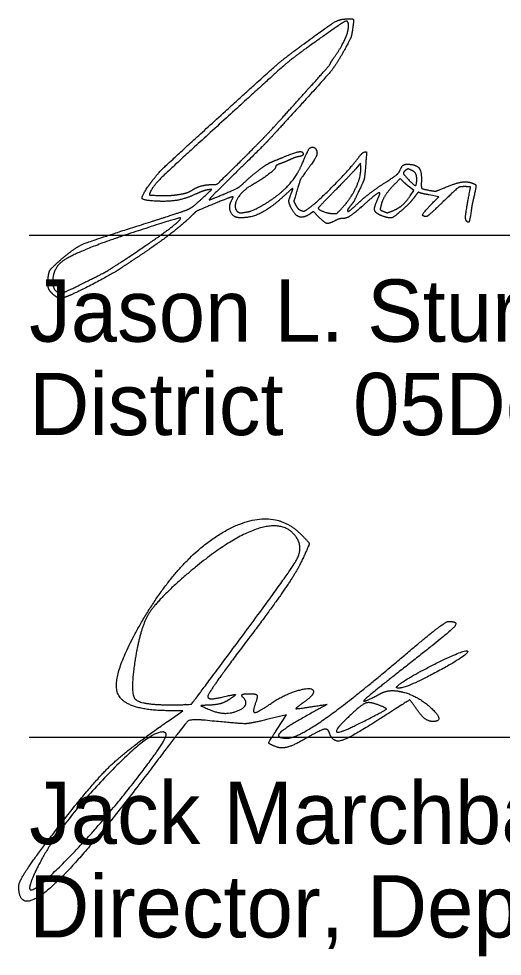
# Model space of a CAD drawing. Extents: x 0 to 34, y 0 to 22.
# Drawn here: x 24.451 to 25.538, y 5.969 to 8.077 of the extents above; entities that cross this region are included whole.
import ezdxf

# ---------------------------------------------------------------- set-up
doc = ezdxf.new("R2010")
doc.units = 0
doc.layers.add('SH_Data', color=7, linetype='Continuous')
doc.layers.add('SH_Text', color=7, linetype='Continuous')

msp = doc.modelspace()

# ---------------------------------------------------------------- linework, layer by layer
at = {"layer": 'SH_Data'}
for p, q in [((24.4745, 7.5907), (27.9745, 7.5907)), ((24.4745, 6.4613), (27.9745, 6.4613))]:
    msp.add_line(p, q, dxfattribs=at)
for points in [[(25.22, 7.7426), (25.2196, 7.7519), (25.2085, 7.7393)], [(25.3157, 7.7106), (25.3085, 7.7177), (25.2971, 7.7061)], [(25.3307, 7.6785), (25.3392, 7.6911), (25.331, 7.6973)], [(25.3854, 7.6669), (25.3951, 7.6769), (25.3736, 7.6809)], [(25.1244, 7.6324), (25.1134, 7.6435), (25.1063, 7.6385)]]:
    msp.add_lwpolyline(points, dxfattribs=at)
for points in [[(25.0877, 8.0173), (25.1488, 8.0622), (25.1709, 8.0755), (25.1857, 8.0765)], [(25.1857, 8.0765), (25.2019, 8.0777), (25.2045, 8.0734), (25.2012, 8.0517)], [(25.1922, 8.0585), (25.1929, 8.0751), (25.1758, 8.0668), (25.1061, 8.0167)], [(25.163, 7.9942), (25.176, 8.0125), (25.1917, 8.0471), (25.1922, 8.0585)], [(25.2012, 8.0517), (25.1993, 8.0387), (25.195, 8.0282), (25.1833, 8.007)], [(24.9157, 7.8692), (25.0139, 7.9585), (25.0501, 7.9897), (25.0877, 8.0173)], [(25.1061, 8.0167), (25.0653, 7.9874), (25.0384, 7.9641), (24.9177, 7.854)], [(25.1833, 8.007), (25.1652, 7.9743), (25.1413, 7.9448), (25.0659, 7.8622)], [(25.1518, 7.977), (25.1518, 7.9778), (25.1569, 7.9856), (25.163, 7.9942)], [(25.1087, 7.9266), (25.1396, 7.9609), (25.1517, 7.975), (25.1518, 7.977)], [(25.0436, 7.8544), (25.0656, 7.8788), (25.0948, 7.9113), (25.1087, 7.9266)], [(24.7424, 7.7004), (24.7597, 7.7252), (24.7933, 7.7579), (24.9157, 7.8692)], [(24.9177, 7.854), (24.7919, 7.7393), (24.7517, 7.6998), (24.7458, 7.685)], [(25.0659, 7.8622), (25.0135, 7.8048), (24.9973, 7.7881), (24.9126, 7.7048)], [(24.9503, 7.7572), (24.9797, 7.7863), (25.0217, 7.83), (25.0436, 7.8544)], [(25.0487, 7.767), (25.073, 7.777), (25.0905, 7.7792), (25.0902, 7.7722)], [(25.0881, 7.7506), (25.1005, 7.7795), (25.1062, 7.7884), (25.1119, 7.7882)], [(25.1197, 7.7824), (25.1231, 7.7752), (25.1172, 7.7615), (25.1007, 7.7386)], [(25.1119, 7.7882), (25.1147, 7.7881), (25.1182, 7.7855), (25.1197, 7.7824)], [(24.886, 7.7042), (24.8966, 7.7044), (24.8984, 7.7059), (24.9503, 7.7572)], [(25.0183, 7.7546), (25.022, 7.756), (25.0357, 7.7616), (25.0487, 7.767)], [(25.0607, 7.76), (25.054, 7.7569), (25.0441, 7.7528), (25.0385, 7.7508)], [(25.0814, 7.7671), (25.0766, 7.7663), (25.0673, 7.7631), (25.0607, 7.76)], [(25.0902, 7.7722), (25.0901, 7.7701), (25.0862, 7.7679), (25.0814, 7.7671)], [(25.1038, 7.6516), (25.1209, 7.6637), (25.196, 7.7394), (25.2108, 7.7595)], [(25.2108, 7.7595), (25.2178, 7.769), (25.2257, 7.777), (25.2284, 7.7774)], [(25.2284, 7.7774), (25.233, 7.7781), (25.2331, 7.7763), (25.2307, 7.7471)], [(24.957, 7.7078), (24.9716, 7.722), (25.0099, 7.7512), (25.0183, 7.7546)], [(25.0283, 7.7433), (25.0281, 7.7389), (24.9978, 7.7159), (24.9741, 7.7022)], [(25.0385, 7.7508), (25.033, 7.7489), (25.0284, 7.7455), (25.0283, 7.7433)], [(25.0332, 7.6804), (25.0521, 7.695), (25.0792, 7.7297), (25.0881, 7.7506)], [(25.1007, 7.7386), (25.0844, 7.7161), (25.0838, 7.715), (25.0761, 7.6889)], [(25.2085, 7.7393), (25.2025, 7.7324), (25.181, 7.7101), (25.161, 7.6898)], [(25.1769, 7.6502), (25.1968, 7.671), (25.2209, 7.7226), (25.22, 7.7426)], [(25.2307, 7.7471), (25.2286, 7.7208), (25.2269, 7.7133), (25.2202, 7.6992)], [(25.3074, 7.7345), (25.312, 7.7451), (25.3184, 7.7502), (25.3267, 7.7498)], [(25.3217, 7.7369), (25.3151, 7.7319), (25.3166, 7.7264), (25.3274, 7.7152)], [(25.3332, 7.7365), (25.3274, 7.7392), (25.3249, 7.7393), (25.3217, 7.7369)], [(25.3267, 7.7498), (25.3452, 7.749), (25.3571, 7.7333), (25.3561, 7.7107)], [(25.3456, 7.712), (25.3461, 7.7236), (25.3415, 7.7327), (25.3332, 7.7365)], [(25.2725, 7.7071), (25.2929, 7.7202), (25.3056, 7.7301), (25.3074, 7.7345)], [(25.3274, 7.7152), (25.3398, 7.7023), (25.3451, 7.7014), (25.3456, 7.712)], [(24.7607, 7.6667), (24.731, 7.6681), (24.7261, 7.677), (24.7424, 7.7004)], [(24.8389, 7.6906), (24.8509, 7.698), (24.8716, 7.704), (24.886, 7.7042)], [(24.9126, 7.7048), (24.8936, 7.6861), (24.8784, 7.6704), (24.8789, 7.6699)], [(24.9128, 7.683), (24.937, 7.6932), (24.949, 7.6999), (24.957, 7.7078)], [(24.9741, 7.7022), (24.9583, 7.693), (24.9381, 7.6681), (24.9377, 7.6571)], [(25.0668, 7.6954), (25.066, 7.6954), (25.0578, 7.6883), (25.0484, 7.6796)], [(25.0638, 7.6846), (25.0662, 7.6905), (25.0675, 7.6953), (25.0668, 7.6954)], [(25.2202, 7.6992), (25.2065, 7.6702), (25.2035, 7.6646), (25.1967, 7.6563)], [(25.2179, 7.6657), (25.2304, 7.6771), (25.2549, 7.6957), (25.2725, 7.7071)], [(25.2971, 7.7061), (25.2821, 7.6909), (25.2682, 7.6693), (25.2654, 7.6571)], [(25.331, 7.6973), (25.3265, 7.7007), (25.3196, 7.7067), (25.3157, 7.7106)], [(25.3561, 7.7107), (25.3555, 7.697), (25.3586, 7.6941), (25.3768, 7.6907)], [(25.3768, 7.6907), (25.3862, 7.689), (25.3914, 7.6901), (25.4082, 7.6971)], [(25.459, 7.6993), (25.4434, 7.7), (25.4351, 7.6947), (25.403, 7.6635)], [(25.4082, 7.6971), (25.4308, 7.7066), (25.4569, 7.7116), (25.4673, 7.7085)], [(25.4649, 7.6892), (25.4667, 7.6986), (25.4665, 7.699), (25.459, 7.6993)], [(25.4673, 7.7085), (25.4781, 7.7053), (25.4795, 7.6992), (25.4746, 7.6787)], [(24.7458, 7.685), (24.7442, 7.6809), (24.7462, 7.6804), (24.766, 7.6795)], [(24.848, 7.6822), (24.8257, 7.672), (24.7881, 7.6654), (24.7607, 7.6667)], [(24.766, 7.6795), (24.7781, 7.679), (24.7973, 7.6799), (24.8086, 7.6816)], [(24.8086, 7.6816), (24.8206, 7.6833), (24.8332, 7.6871), (24.8389, 7.6906)], [(24.8293, 7.6474), (24.8364, 7.6503), (24.8503, 7.6607), (24.8633, 7.6728)], [(24.876, 7.6921), (24.871, 7.6914), (24.8583, 7.6869), (24.848, 7.6822)], [(24.8633, 7.6728), (24.885, 7.6932), (24.8852, 7.6934), (24.876, 7.6921)], [(24.8789, 7.6699), (24.8793, 7.6694), (24.8946, 7.6753), (24.9128, 7.683)], [(24.9325, 7.6766), (24.9318, 7.6773), (24.9129, 7.6703), (24.8905, 7.661)], [(24.9302, 7.6696), (24.9321, 7.6727), (24.9331, 7.6759), (24.9325, 7.6766)], [(25.0484, 7.6796), (25.0172, 7.6506), (24.972, 7.6284), (24.9464, 7.6295)], [(24.9669, 7.643), (24.9759, 7.6446), (25.0163, 7.6673), (25.0332, 7.6804)], [(25.0625, 7.6535), (25.0581, 7.6632), (25.0584, 7.6711), (25.0638, 7.6846)], [(25.0761, 7.6889), (25.0695, 7.6665), (25.0694, 7.666), (25.0739, 7.6574)], [(25.161, 7.6898), (25.1409, 7.6694), (25.1244, 7.652), (25.1244, 7.651)], [(25.2628, 7.6843), (25.2629, 7.6882), (25.2453, 7.6753), (25.2211, 7.6537)], [(25.2583, 7.6721), (25.2607, 7.6772), (25.2627, 7.6827), (25.2628, 7.6843)], [(25.2913, 7.6449), (25.305, 7.6507), (25.3212, 7.6645), (25.3307, 7.6785)], [(25.3411, 7.6768), (25.3368, 7.6705), (25.3253, 7.6581), (25.3156, 7.6493)], [(25.3506, 7.6866), (25.3498, 7.6874), (25.3455, 7.683), (25.3411, 7.6768)], [(25.3736, 7.6809), (25.3617, 7.6831), (25.3514, 7.6857), (25.3506, 7.6866)], [(25.4573, 7.6222), (25.4546, 7.6252), (25.4572, 7.6488), (25.4649, 7.6892)], [(25.4746, 7.6787), (25.4722, 7.6687), (25.4691, 7.6529), (25.4678, 7.6435)], [(24.8905, 7.661), (24.8555, 7.6466), (24.8478, 7.6424), (24.8373, 7.6316)], [(24.9464, 7.6295), (24.9325, 7.6301), (24.9221, 7.6559), (24.9302, 7.6696)], [(24.9377, 7.6571), (24.9373, 7.6487), (24.946, 7.6397), (24.9535, 7.6408)], [(25.1063, 7.6385), (25.0918, 7.6281), (25.071, 7.6352), (25.0625, 7.6535)], [(25.0739, 7.6574), (25.0764, 7.6527), (25.0815, 7.6476), (25.0853, 7.6461)], [(25.2211, 7.6537), (25.2024, 7.637), (25.1853, 7.6272), (25.1755, 7.6275)], [(25.19, 7.6467), (25.1898, 7.6418), (25.1979, 7.6474), (25.2179, 7.6657)], [(25.1967, 7.6563), (25.1931, 7.6518), (25.1901, 7.6475), (25.19, 7.6467)], [(25.2672, 7.6339), (25.2527, 7.6394), (25.2494, 7.6533), (25.2583, 7.6721)], [(25.2654, 7.6571), (25.2635, 7.6485), (25.2639, 7.647), (25.2693, 7.6446)], [(25.3671, 7.6322), (25.3568, 7.6327), (25.3621, 7.6427), (25.3854, 7.6669)], [(25.403, 7.6635), (25.3852, 7.6462), (25.3691, 7.6321), (25.3671, 7.6322)], [(24.8373, 7.6316), (24.8216, 7.6156), (24.756, 7.5656), (24.7207, 7.5426)], [(24.7531, 7.6222), (24.7884, 7.6334), (24.8226, 7.6448), (24.8293, 7.6474)], [(24.9535, 7.6408), (24.9567, 7.6414), (24.9628, 7.6424), (24.9669, 7.643)], [(25.0853, 7.6461), (25.091, 7.6438), (25.0939, 7.6446), (25.1038, 7.6516)], [(25.1244, 7.651), (25.1242, 7.6478), (25.1458, 7.6396), (25.1559, 7.639)], [(25.1614, 7.6224), (25.1484, 7.6156), (25.1385, 7.6182), (25.1244, 7.6324)], [(25.1559, 7.639), (25.1642, 7.6385), (25.1671, 7.64), (25.1769, 7.6502)], [(25.3156, 7.6493), (25.296, 7.6313), (25.2841, 7.6275), (25.2672, 7.6339)], [(25.2693, 7.6446), (25.278, 7.6406), (25.2813, 7.6407), (25.2913, 7.6449)], [(25.4678, 7.6435), (25.465, 7.6238), (25.4618, 7.6173), (25.4573, 7.6222)], [(24.546, 7.5355), (24.5781, 7.563), (24.6147, 7.5783), (24.7531, 7.6222)], [(24.8145, 7.629), (24.8132, 7.6304), (24.6827, 7.5884), (24.6401, 7.5728)], [(24.6977, 7.5409), (24.7573, 7.5804), (24.8175, 7.6257), (24.8145, 7.629)], [(25.1755, 7.6275), (25.1731, 7.6275), (25.1667, 7.6253), (25.1614, 7.6224)], [(24.6401, 7.5728), (24.57, 7.5471), (24.5286, 7.5161), (24.5274, 7.4884)], [(24.5169, 7.4889), (24.5176, 7.5055), (24.5253, 7.5177), (24.546, 7.5355)], [(24.5927, 7.4807), (24.644, 7.5063), (24.654, 7.5121), (24.6977, 7.5409)], [(24.7207, 7.5426), (24.7058, 7.5329), (24.6864, 7.52), (24.6777, 7.514)], [(24.6777, 7.514), (24.6629, 7.5039), (24.5767, 7.4589), (24.5592, 7.4522)], [(24.5302, 7.4557), (24.5207, 7.4639), (24.5163, 7.4749), (24.5169, 7.4889)], [(24.5274, 7.4884), (24.5268, 7.4753), (24.5369, 7.4607), (24.547, 7.4601)], [(24.547, 7.4601), (24.5491, 7.4599), (24.5696, 7.4692), (24.5927, 7.4807)], [(24.5592, 7.4522), (24.5479, 7.4479), (24.5379, 7.4491), (24.5302, 7.4557)]]:
    msp.add_open_spline(points, degree=2, dxfattribs=at)
at = {"layer": 'SH_Text'}
for p, q in [((24.9368, 6.6663), (24.9368, 6.6663)), ((25.3021, 6.5765), (25.3021, 6.5765)), ((25.2573, 6.5348), (25.2573, 6.5348))]:
    msp.add_line(p, q, dxfattribs=at)
for points in [[(24.7892, 6.4994), (24.8198, 6.5206), (24.782, 6.5212)], [(25.0321, 6.4795), (25.0533, 6.5119), (25.0116, 6.5018)]]:
    msp.add_lwpolyline(points, dxfattribs=at)
for points in [[(24.7255, 6.7171), (24.8117, 6.8674), (25.0199, 6.9835), (25.0855, 6.9178)], [(25.0766, 6.9086), (25.0506, 6.9506), (24.9245, 6.9095), (24.8292, 6.8279)], [(25.0855, 6.9178), (25.1043, 6.899), (25.1043, 6.894), (25.086, 6.8556)], [(24.9368, 6.6663), (25.0582, 6.8298), (25.0906, 6.886), (25.0766, 6.9086)], [(25.086, 6.8556), (25.0751, 6.8326), (25.0233, 6.757), (24.9711, 6.6877)], [(24.8292, 6.8279), (24.7625, 6.7708), (24.7237, 6.7067), (24.7126, 6.6355)], [(24.782, 6.5212), (24.6841, 6.5229), (24.6607, 6.6041), (24.7255, 6.7171)], [(25.3156, 6.6436), (25.3661, 6.6864), (25.4116, 6.7216), (25.4167, 6.7217)], [(25.4167, 6.7217), (25.4416, 6.7222), (25.4182, 6.6966), (25.3323, 6.6294)], [(24.9711, 6.6877), (24.9188, 6.6183), (24.8761, 6.5576), (24.8761, 6.5529)], [(24.7907, 6.5344), (24.8373, 6.5344), (24.8419, 6.5385), (24.9368, 6.6663)], [(25.0543, 6.4594), (25.0773, 6.4594), (25.2034, 6.5482), (25.3156, 6.6436)], [(25.3021, 6.5765), (25.3225, 6.5943), (25.4546, 6.6601), (25.4597, 6.6549)], [(25.4597, 6.6549), (25.4659, 6.6488), (25.3233, 6.5719), (25.3056, 6.5719)], [(24.7126, 6.6355), (24.7012, 6.5621), (24.7226, 6.5344), (24.7907, 6.5344)], [(25.3323, 6.6294), (25.2391, 6.5564), (25.2177, 6.5348), (25.2616, 6.5583)], [(24.9105, 6.5522), (24.936, 6.5581), (24.94, 6.5569), (24.9261, 6.5475)], [(24.9552, 6.5511), (24.9506, 6.5557), (24.9569, 6.5594), (24.9691, 6.5594)], [(24.9691, 6.5594), (24.9837, 6.5594), (24.9888, 6.553), (24.9841, 6.5406)], [(25.0202, 6.5388), (25.0491, 6.5586), (25.1136, 6.5761), (25.1136, 6.5641)], [(25.1136, 6.5641), (25.1136, 6.5596), (25.1039, 6.5488), (25.092, 6.5401)], [(25.2616, 6.5583), (25.2742, 6.5651), (25.2981, 6.5672), (25.3147, 6.563)], [(25.3056, 6.5719), (25.3008, 6.5719), (25.2993, 6.5739), (25.3021, 6.5765)], [(25.3147, 6.563), (25.3508, 6.5538), (25.4092, 6.4969), (25.3825, 6.4969)], [(24.8761, 6.5529), (24.8761, 6.5481), (24.8916, 6.5478), (24.9105, 6.5522)], [(24.9261, 6.5475), (24.9158, 6.5405), (24.8961, 6.5343), (24.8823, 6.5338)], [(24.8865, 6.5211), (24.9164, 6.5091), (24.9726, 6.5337), (24.9552, 6.5511)], [(24.9841, 6.5406), (24.9751, 6.5174), (24.988, 6.5167), (25.0202, 6.5388)], [(25.092, 6.5401), (25.0731, 6.5263), (25.075, 6.525), (25.1076, 6.5299)], [(25.1076, 6.5299), (25.1444, 6.5355), (25.1442, 6.5352), (25.0988, 6.5101)], [(25.2573, 6.5348), (25.2401, 6.5411), (25.2236, 6.536), (25.2042, 6.5183)], [(25.2292, 6.4985), (25.2756, 6.5222), (25.2792, 6.5268), (25.2573, 6.5348)], [(25.3477, 6.5216), (25.3309, 6.5456), (25.3288, 6.5452), (25.2631, 6.5028)], [(24.8823, 6.5338), (24.8599, 6.5329), (24.8604, 6.5316), (24.8865, 6.5211)], [(25.2042, 6.5183), (25.16, 6.4778), (25.1712, 6.4689), (25.2292, 6.4985)], [(25.3825, 6.4969), (25.3729, 6.4969), (25.3572, 6.508), (25.3477, 6.5216)], [(24.5382, 6.2572), (24.6159, 6.3576), (24.6959, 6.4349), (24.7892, 6.4994)], [(24.8704, 6.4995), (24.837, 6.5028), (24.8252, 6.4923), (24.7486, 6.3906)], [(25.0116, 6.5018), (24.9712, 6.492), (24.9489, 6.4917), (24.8704, 6.4995)], [(25.0988, 6.5101), (25.0477, 6.4819), (25.028, 6.4594), (25.0543, 6.4594)], [(25.2631, 6.5028), (25.1942, 6.4585), (25.1567, 6.4487), (25.1486, 6.4731)], [(24.782, 6.4701), (24.7611, 6.491), (24.5426, 6.2654), (24.4963, 6.175)], [(25.0309, 6.4395), (25.0127, 6.4465), (25.0128, 6.4501), (25.0321, 6.4795)], [(25.1486, 6.4731), (25.1458, 6.4816), (25.1265, 6.4764), (25.0975, 6.4593)], [(24.5664, 6.1938), (24.634, 6.2628), (24.7897, 6.4624), (24.782, 6.4701)], [(25.0975, 6.4593), (25.0718, 6.4442), (25.0419, 6.4353), (25.0309, 6.4395)], [(24.7486, 6.3906), (24.5962, 6.1886), (24.4511, 6.0599), (24.4511, 6.1269)], [(24.4511, 6.1269), (24.4511, 6.1366), (24.4903, 6.1952), (24.5382, 6.2572)], [(24.4963, 6.175), (24.465, 6.1141), (24.4967, 6.1225), (24.5664, 6.1938)]]:
    msp.add_open_spline(points, degree=2, dxfattribs=at)

# ---------------------------------------------------------------- texts
for s, p in [('Jason L. Sturgeon, P.E.', (24.4745, 7.3507)), ('District       Deputy Director', (24.4745, 7.1407)), ('              05', (24.4745, 7.1407)), ('Jack Marchbanks, PhD', (24.4745, 6.2213)), ('Director, Department of Transportation', (24.4745, 6.0113))]:
    msp.add_text(s, height=0.14, dxfattribs=at).set_placement(p)

doc.saveas('drawing.dxf')
